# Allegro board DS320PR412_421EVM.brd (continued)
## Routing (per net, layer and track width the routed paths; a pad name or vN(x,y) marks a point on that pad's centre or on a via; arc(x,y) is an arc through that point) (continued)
N16831849: length 2.9
  BOTTOM w0.127: R9.2 JMP3.2
N16831858: length 2.9
  BOTTOM w0.127: R10.2 JMP3.4
N16831867: length 2.9
  BOTTOM w0.127: R11.1 JMP3.6
N16831870: length 2.9
  BOTTOM w0.127: R12.2 JMP3.8
N16832723: length 2.9
  BOTTOM w0.127: R21.2 JMP4.2
N16832755: length 2.9
  BOTTOM w0.127: R22.2 JMP4.4
N16832773: length 2.9
  BOTTOM w0.127: R23.1 JMP4.6
N16832779: length 2.9
  BOTTOM w0.127: R24.2 JMP4.8
N16832807: length 2.9
  BOTTOM w0.127: R25.2 JMP5.2
N16832839: length 2.9
  BOTTOM w0.127: R26.2 JMP5.4
N16832857: length 2.9
  BOTTOM w0.127: R27.1 JMP5.6
N16832863: length 2.9
  BOTTOM w0.127: R28.2 JMP5.8
N16832891: length 2.9
  BOTTOM w0.127: R29.2 JMP6.2
N16832923: length 2.9
  BOTTOM w0.127: R30.2 JMP6.4
N16832941: length 2.9
  BOTTOM w0.127: R39.1 JMP6.6
N16832947: length 2.9
  BOTTOM w0.127: R40.2 JMP6.8
N16833662: length 2.9
  BOTTOM w0.127: R49.2 JMP9.2
N16833694: length 2.9
  BOTTOM w0.127: R50.2 JMP9.4
N16833712: length 2.9
  BOTTOM w0.127: R51.1 JMP9.6
N16833718: length 2.9
  BOTTOM w0.127: R52.2 JMP9.8
N16833746: length 2.9
  BOTTOM w0.127: R53.2 JMP10.2
N16833778: length 2.9
  BOTTOM w0.127: R62.2 JMP10.4
N16833796: length 2.9
  BOTTOM w0.127: R63.1 JMP10.6
N16833802: length 2.9
  BOTTOM w0.127: R64.2 52.96,128.98
N16833830: length 2.9
  BOTTOM w0.127: R65.2 JMP11.2
N16833862: length 2.9
  BOTTOM w0.127: R66.2 JMP11.4
N16833880: length 2.9
  BOTTOM w0.127: R67.1 JMP11.6
N16833886: length 2.9
  BOTTOM w0.127: R68.2 JMP11.8
N16835436: length 2.9
  BOTTOM w0.127: R133.2 JMP14.2
N16835468: length 2.9
  BOTTOM w0.127: R134.2 74.04,128.98
N16835486: length 2.9
  BOTTOM w0.127: R135.1 JMP14.6
N16835492: length 2.9
  BOTTOM w0.127: R136.2 79.12,128.98
N16835520: length 2.9
  BOTTOM w0.127: R137.2 JMP15.2
N16835552: length 2.9
  BOTTOM w0.127: R138.2 JMP15.4
N16835570: length 2.9
  BOTTOM w0.127: R139.1 JMP15.6
N16835576: length 2.9
  BOTTOM w0.127: R140.2 JMP15.8
N16835604: length 2.9
  BOTTOM w0.127: R141.2 JMP16.2
N16835636: length 2.9
  BOTTOM w0.127: R142.2 JMP16.4
N16835654: length 2.9
  BOTTOM w0.127: R143.1 JMP16.6
N16835660: length 2.9
  BOTTOM w0.127: R144.2 JMP16.8
N16837171: length 2.6
  BOTTOM w0.127: R13.2 J30.2
N16837180: length 2.6
  BOTTOM w0.127: R14.2 J30.4
N16837189: length 2.6
  BOTTOM w0.127: R15.1 J30.6
N16837198: length 2.6
  BOTTOM w0.127: R16.2 J30.8
N16837577: length 2.6
  BOTTOM w0.127: R17.2 J23.2
N16837609: length 2.6
  BOTTOM w0.127: R18.2 J23.4
N16837629: length 2.6
  BOTTOM w0.127: R19.1 J23.6
N16837647: length 2.6
  BOTTOM w0.127: R20.2 J23.8
N16841214: length 2.6
  BOTTOM w0.127: R41.2 J24.2
N16841246: length 2.6
  BOTTOM w0.127: R42.2 J24.4
N16841266: length 2.6
  BOTTOM w0.127: R43.1 J24.6
N16841284: length 2.6
  BOTTOM w0.127: R44.2 J24.8
N16842142: length 2.6
  BOTTOM w0.127: R45.2 J25.2
N16842174: length 2.6
  BOTTOM w0.127: R46.2 J25.4
N16842194: length 2.6
  BOTTOM w0.127: R47.1 146.18,117.42
N16842212: length 2.6
  BOTTOM w0.127: R48.2 J25.8
N16843638: length 2.6
  BOTTOM w0.127: R69.2 J26.2
N16843670: length 2.6
  BOTTOM w0.127: R70.2 J26.4
N16843690: length 2.6
  BOTTOM w0.127: R71.1 J26.6
N16843708: length 2.6
  BOTTOM w0.127: R72.2 J26.8
N16844326: length 2.6
  BOTTOM w0.127: R73.2 J27.2
N16844358: length 2.6
  BOTTOM w0.127: R74.2 J27.4
N16844378: length 2.6
  BOTTOM w0.127: R75.1 J27.6
N16844396: length 2.6
  BOTTOM w0.127: R76.2 J27.8
N16846395: length 2.6
  BOTTOM w0.127: R145.2 J28.2
N16846427: length 2.6
  BOTTOM w0.127: R146.2 J28.4
N16846447: length 2.6
  BOTTOM w0.127: R147.1 J28.6
N16846465: length 2.6
  BOTTOM w0.127: R148.2 J28.8
N16847091: length 2.6
  BOTTOM w0.127: R149.2 J29.2
N16847123: length 2.6
  BOTTOM w0.127: R150.2 J29.4
N16847143: length 2.6
  BOTTOM w0.127: R151.1 J29.6
N16847161: length 2.6
  BOTTOM w0.127: R152.2 J29.8

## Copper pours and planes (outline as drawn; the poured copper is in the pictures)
+3.3V on TOP: 1.27,25.43 4.6,25.43 5,25.02 5,21.23 4.98,21.21 4.98,20.09 5.61,19.46 15.11,19.46 16.48,20.83 16.48,25.45 18.54,25.45 19,24.99 19,21.01 20.55,19.46 28.91,19.46 30.33,20.88 30.33,25.5 32.49,25.5 32.92,25.07 32.92,21.31 34.85,19.38 42.62,19.38 44.37,21.13 44.37,25.35 44.35,25.37 46.35,25.37 46.86,24.87 46.86,17.45 45.82,16.41 4.14,16.41 1.24,19.3 1.24,25.4
+3.3V on TOP: 12.9,74.22 12.9,71.11 13.62,70.39 20.8,70.39 21.56,71.15 21.56,73.97 20.8,74.73 13.41,74.73
+3.3V on TOP: 23.42,90.7 26.56,90.7 26.77,90.91 26.77,101.1 26.79,101.13 26.42,101.51 23.64,101.51 23.21,101.07 23.21,90.91
+3.3V on L3_SIG: 162.05,84 162.05,111.2 47.45,111.2 38.13,120.52 8.31,120.52 4.57,116.79 4.57,111.25 4.62,111.2 4.62,92.38 8.75,88.25 8.75,82.24 6.5,80 6.5,40.74 1.22,35.46 1.22,16.38 37.78,16.38 37.78,36.26 37.08,36.96 17.4,36.96 16.72,37.63 16.72,66.8 28.19,78.27 28.19,104.85 156.72,104.85 156.72,84
+3.3VA on TOP: 54.31,2.62 54.31,23.52 54.79,24 54.79,48.11 55.09,48.41 55.09,50.77 55.63,50.77 55.75,50.65 55.75,23.19 54.99,22.43 54.99,2.62
+3.3VA on TOP: 55.09,91.41 55.63,91.41 55.75,91.29 55.75,86.72 54.79,86.72 54.79,89 55.09,89.31
+3.3VA on BOTTOM: 55.01,46.06 55.01,53.05 57.45,55.49 57.45,81.08 54.18,84.35 54.18,88.02 55.23,89.06 55.5,89.06 55.66,88.9 55.66,85.45 55.64,85.42 55.64,84.43 58.02,82.05 58.02,54.87 55.92,52.77 55.92,46.5 55.48,46.06
+3V on TOP: 53.11,48.82 53.09,48.84 53.09,52.96 54.08,53.95 54.08,58.47 52.4,60.15 45.99,60.15 44.78,58.94 42.03,58.94 41.83,59.15 41.83,61.14 43.45,62.76 53.81,62.76 55.8,60.77 55.8,53.42 53.8,51.41 53.8,48.82
+3V on TOP: 53.09,89.48 53.09,93.6 54.08,94.59 54.08,99.11 53.6,99.58 42.03,99.58 41.83,99.79 41.83,101.78 42.09,102.03 55.18,102.03 55.8,101.41 55.8,94.06 53.8,92.05 53.8,89.46 53.11,89.46
+3V on TOP: 52.32,2.62 52.32,16.71 53.01,16.71 53.01,2.62
+3V on BOTTOM: 3.96,29.59 3.96,33.28 13.05,33.28 13.83,32.49 13.83,29.57 17.96,29.57 17.96,33.32 28.22,33.32 28.85,32.69 28.85,29.59 31.83,29.59 31.83,33.63 40.77,33.63 42.12,32.28 42.12,29.62 45.85,29.62 45.85,37.54 45.13,38.26 2.77,38.26 1.11,36.61 1.11,29.59
+3V on BOTTOM: 54.99,2.62 54.99,15.37 52.31,15.37 52.31,8.3 53.14,7.47 53.14,5.92 53.29,5.92 53.29,2.62
+3V on L4_SIG: 44.42,102.39 44.42,46.89 46.06,45.25 46.06,28.03 55.19,18.9 55.19,11.2 52.11,11.2 52.11,15.3 41.67,25.73 41.67,31.6 38.84,34.44 38.84,36.68 40.51,38.35 40.51,102.31 40.67,102.48 44.34,102.48
+12V on TOP: 13.06,87.3 16,87.3 16.01,87.29 16.01,85.06 15.96,85.01 12.4,85.01 11.99,84.61 11.99,82.98 11.91,82.9 8.46,82.9 7.35,81.79 3.71,81.79 3.71,84.91 3.73,84.89 6.71,84.89 7.49,85.67 9.55,85.67 9.55,86.66 12.42,86.66
+12V on TOP: 45.75,11 48.01,11 48.01,2.62 45.36,2.62 45.36,5.59 45.72,5.59 45.75,5.61
+12V on TOP: 47.07,57.99 48.74,57.99 48.79,57.94 48.79,46.35 48.72,46.28 46.18,46.28 46.08,46.38 46.08,52.65 47.09,53.67 47.09,57.96
+12V on TOP: 47.07,98.63 48.74,98.63 48.79,98.58 48.79,86.99 48.72,86.92 46.18,86.92 46.08,87.02 46.08,93.29 47.09,94.31 47.09,98.6
+12V on BOTTOM: 46.28,2.62 46.28,11 48.01,11 48.01,2.62
+12V on BOTTOM: 12.17,86.1 23.34,86.1 23.46,86.23 48.59,86.23 48.98,86.62 48.98,88.99 48.59,89.38 31.39,89.38 28.88,91.89 8.24,91.89 7.11,90.76 7.14,90.73 7.14,85.47 6.58,84.91 6.38,84.91 6.35,84.94 3.73,84.94 3.73,81.79 12.17,81.79
+12V on L3_SIG: 46.43,90.91 48.4,90.91 48.93,90.38 48.93,86.52 47.04,84.62 47.04,58.24 45.76,56.96 45.76,51.81 47.93,49.64 47.96,49.64 48.88,48.73 48.88,45.72 47.29,44.14 47.29,16.61 49.71,14.19 49.71,6.16 49.71,6.15 49.71,5.53 49.57,5.39 45.72,5.39 45.72,12.57 44.69,13.59 41.27,13.59 40.4,14.47 40.4,17.91 39.01,19.29 39.01,36.88 40.4,38.26 40.4,84.87
GND on TOP: 48.36,2.62 48.36,7.21 48.97,7.21 48.97,2.62
GND on TOP: 18.67,64.98 20.19,64.98 20.53,64.64 20.53,62.39 20.33,62.2 18.67,62.2 18.52,62.35 18.52,64.82
GND on TOP: 7.44,89.61 16.21,89.61 20.01,93.41 20.01,102.84 20.51,103.34 28.61,103.34 29.89,102.06 29.89,93.55 27.3,93.55 27.09,93.76 27.09,101.35 26.69,101.75 23.35,101.75 22.96,101.37 22.96,98.72 22.65,98.41 22.65,88.15 20.49,88.15 19.72,87.38 19.72,81.77 19.6,81.65 16.43,81.65 16.26,81.82 16.26,82.42 16.17,82.5 15.12,82.5 15.04,82.58 14.57,82.58 13.89,83.26 12.93,83.26 12.93,84.05 13.87,84.05 14.62,83.3 16.14,83.3 16.32,83.48 16.32,87.29 15.98,87.63 12.9,87.63 12.75,87.48 9.17,87.48 9.14,87.5 9.14,86.39 7.47,86.39 7.42,86.44 7.42,87.63
GND on BOTTOM: 112.34,23.01 112.34,21 112.63,20.71 122.45,20.71 123.34,19.82 125.44,19.82 125.98,20.36 126.83,20.36 127.05,20.14 127.67,20.14 128.37,20.85 128.37,23.08 127.93,23.53 112.86,23.53
GND on BOTTOM: 72.5,22.95 88.71,22.95 89.1,22.55 89.1,20.82 88.95,20.67 87.73,20.67 87.16,20.1 84.29,20.1 83.64,20.74 72.45,20.74 72.32,20.87 72.32,22.76
GND on BOTTOM: 92.39,20.55 92.39,22.92 92.77,23.29 108.05,23.29 108.56,22.78 108.56,20.41 108.38,20.23 106.85,20.23 106.82,20.26 106.64,20.26 106.16,19.78 103.14,19.78 102.93,19.98 102.93,20.39 102.6,20.72 93.38,20.72 93.09,20.43 92.52,20.43
GND on BOTTOM: 48.36,2.62 48.97,2.62 48.97,7.21 48.36,7.21
GND on BOTTOM: 54.24,22.23 57.65,22.23 58.51,23.09 69.31,23.09 70.01,22.39 70.01,20.83 69.67,20.49 64.14,20.49 63.94,20.29 63.94,19.87 63.83,19.75 60.45,19.75 60.41,19.8 60.41,20.39 60.19,20.62 59.12,20.62 58.89,20.39 58.89,20.03 58.66,19.8 54.51,19.8 53.89,20.42 53.89,21.88
GND on L2_GND: 89.53,5.64 128.65,5.64 128.65,13.41 186.92,13.41 186.92,135.97 0.64,135.97 0.64,5.16 14.35,5.16 14.35,13.41 34.04,13.41 34.04,5.16 40.64,5.16 40.64,11 41.39,12.75 43.18,13.41 44.9,12.67 45.72,11 45.72,5.64 55.75,5.64 55.75,7.44 57.15,8.84 58.55,7.44 58.55,5.64 89.51,5.64 89.53,-65.33 154.94,-65.33 154.94,-61.52 89.56,-61.52 ; 74 cut-outs
GND on L5_GND: 89.53,5.64 128.65,5.64 128.65,13.41 186.87,13.41 186.87,135.97 0.64,135.97 0.64,5.16 14.35,5.16 14.35,13.41 34.04,13.41 34.04,5.16 40.64,5.16 40.64,11 41.39,12.75 43.18,13.41 44.9,12.67 45.72,11 45.72,5.64 55.75,5.64 55.75,7.44 57.15,8.84 58.55,7.44 58.55,5.64 89.51,5.64 89.53,-65.33 154.94,-65.33 154.94,-61.52 89.56,-61.52
VCC0 on BOTTOM: 34.39,32.26 34.39,28.75 35.16,27.99 52.49,27.99 54.88,30.38 54.88,32.96 56.49,34.57 108.66,34.57 111.27,31.96 111.27,19.02 110.59,18.34 108.48,18.34 108.16,18.66 104.54,18.66 103.64,17.75 98.59,17.75 98.44,17.9 98.44,19.36 98.65,19.57 102.82,19.57 102.96,19.43 106.72,19.43 106.83,19.55 109.08,19.55 109.29,19.75 109.29,24.24 108.13,25.4 108.13,30.24 107.13,31.24 59.5,31.24 53.88,25.62 34.17,25.62 32.41,27.38 32.41,32.26
VCC1 on BOTTOM: 46.35,29.64 46.35,35.92 50.52,40.08 129.98,40.08 133.18,36.89 133.18,19.88 131.9,18.6 123.31,18.6 122.72,18.01 117.65,18.01 117.38,18.28 117.38,19.45 117.48,19.56 118.54,19.56 119.06,19.04 122.41,19.04 122.79,19.42 125.72,19.42 125.85,19.56 129.81,19.56 130.31,20.06 130.31,33 127.6,35.71 124.2,35.71 124.17,35.74 58.98,35.74 58.96,35.72 50.25,35.72 48.41,33.88 48.41,29.64
VCC2 on BOTTOM: 4.47,32.31 6.5,32.31 6.5,26.87 11.59,21.78 49.82,21.78 52.17,19.44 58.78,19.44 58.86,19.36 58.86,18.95 58.99,18.83 60.39,18.83 60.63,19.07 65.28,19.07 65.36,18.99 65.36,18.26 65.24,18.14 57.86,18.14 57.45,18.54 11.4,18.54 4.47,25.45
VCC3 on BOTTOM: 18.41,32.26 20.45,32.26 20.45,27.53 23.29,24.69 55.71,24.69 56.61,25.58 89.93,25.58 92.03,23.48 92.03,19.77 91.07,18.81 85.75,18.81 84.66,17.72 79.23,17.72 79.1,17.85 79.1,19.36 79.33,19.59 80.3,19.59 80.98,18.91 80.98,18.88 83.72,18.88 84.52,19.68 89.49,19.68 90.02,20.21 90.02,22.63 89.21,23.44 57.41,23.44 56.58,22.61 22.38,22.61 18.41,26.57
N16707563 on TOP: 20.06,87.31 20.06,85.01 20.11,84.96 26.65,84.96 27,85.31 27,87.64 26.81,87.84 22.78,87.84 22.27,87.32 20.07,87.32
N16716349 on TOP: 15.32,68.35 19.39,68.35 19.67,68.06 19.67,65.49 19.56,65.37 18.43,65.37 18.14,65.08 18.14,61.97 17.97,61.8 15.47,61.8 15.19,62.08 15.19,63.26 15.45,63.52 16.42,63.52 16.99,64.08 16.99,64.43 17,64.44 17,65.03 16.72,65.31 15.4,65.31 15.13,65.57 15.13,68.16
N16716349 on BOTTOM: 12.93,59.25 12.93,52.17 13.77,51.33 21.54,51.33 22.25,52.04 22.25,57.37 18.15,61.47 18.15,63.4 15.23,63.4 15.23,61.55
N16716349 on L4_SIG: 14.58,61.83 17.28,61.83 17.54,62.09 17.54,63.4 17.28,63.66 14.58,63.66 14.32,63.4 14.32,62.09
N16850880 on TOP: 35.44,32.8 34.96,32.31 34.96,28.49 36.01,27.44 36.01,20.97 35.97,20.93 36.52,20.37 40.4,20.37 40.9,20.87 40.9,31.34 39.44,32.8
N16850966 on TOP: 48.93,32.82 48.93,28.49 48.95,28.47 48.95,26.26 49.98,25.23 49.98,20.97 49.94,20.93 50.49,20.37 52.77,20.37 53.41,21.02 53.41,32.82
N16851615 on TOP: 7.5,32.8 7.02,32.31 7.02,28.49 8.07,27.44 8.07,20.97 8.03,20.93 8.58,20.37 12.46,20.37 12.96,20.87 12.96,31.34 11.5,32.8
N16851807 on TOP: 21.47,32.8 20.99,32.31 20.99,28.49 22.04,27.44 22.04,20.97 22,20.93 22.55,20.37 26.43,20.37 26.93,20.87 26.93,31.34 25.47,32.8

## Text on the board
BOTTOM: LAYER 6 - BOTTOM SIDE
Ref Des/Assembly Bottom: ASSY BOTTOM
Board Geometry/Soldermask Bottom: SOLDERMASK BOTTOM
Package Geometry/Pastemask Bottom: PASTEMASK BOTTOM
Ref Des/Silkscreen Bottom: SILKSCREEN BOTTOM
User.Comments: 1 | 2
TOP: LAYER 1 - TOP SIDE
Ref Des/Assembly Top: ASSY TOP
Board Geometry/Soldermask Top: SOLDERMASK TOP
Package Geometry/Pastemask Top: PASTEMASK TOP
Ref Des/Silkscreen Top: DS160PR421_2 | DS160PR421_3 | DS160PR412_0 | DS160PR412_1 | 3_1 | 2_1 | PRSNT3_1 | PRSNT2_1 | GND | 2_1_B | 2_1_A | 2_3_B | 2_3_A | 2_2 | 2_4 | PRSNT2_2 | PRSNT2_4 | 2_2_B | 2_2_A | 2_4_B | 2_4_A | A | 12V | REFOUT | CLKIN1 | CLKIN0 | DISABLE | ENABLED | DISABLED | SELECT | USB2ANY | AARDVARK | CONN | A+B | B | NC=L4 | CLKIN1- | 3.3V | CLKIN1+ | PCIE | VCC2 | REG | VCC3 | PERRST#A | PERRST#A+B | PERRST#B | L0 | VCC0 | L1 | L2 | L3 | VCC1 | SDA | SCL | PD | PERST_INV | PR421_2_VCC | PR421_3_VCC | PR412_0_VCC | PR412_1_VCC | 421_2 GAIN | 421_2 MODE | 421_2 RX_DET | 421_3 EQ0_ADDR | 421_3 GAIN | 421_3 RX_DET | 412_0 EQ0_ADDR | 412_0 GAIN | 412_0 EQ1 | 412_0 RX_DET | 412_1 GAIN | 412_1 RX_DET | PCIe-A X8 | PCIe-B X16 | SILKSCREEN TOP | LABEL | HSDC110A
L2_GND: LAYER 2 - GND PLANE
L3_SIG: LAYER 3 - SIGNAL
L4_SIG: LAYER 4 - SIGNAL
L5_GND: LAYER 5 - GND PLANE
XSECTION_CHART: * AIR 0 MIL | * SOLDERMASK-0.8MIL 0.8 MIL | L1 COPPER_1/2OZ_PLATED 1.4 MIL | * FILL_RO4450T_3 3 MIL | L2 COPPER_1.0OZ 1.4 MIL | L3 COPPER_1.0OZ 1.4 MIL | * CORE_RO4350B_20 20 MIL | L4 COPPER_1.0OZ 1.4 MIL | L5 COPPER_1.0OZ 1.4 MIL | L6 COPPER_1/2OZ_PLATED 1.4 MIL | DESIGN CROSS SECTION CHART | ___________________________ | TOTAL THICKNESS 62 MIL | 1-6
DIMENSION: FABRICATION DRAWING | CAD ORIGIN | 0.050 | TYP | SCALE: NONE | BEVEL EDGE DETAIL | VIEW A-A
User.6: LAYER 5 | LAYER 1 | LAYER 2 | LAYER 3 | LAYER 4 | LAYER 6 | LAYER | NO. | TABLE 1: | L5_GND | TOP | L2_GND | L3_SIG | L4_SIG | BOTTOM | NAME | DIFFIRENTIAL PAIR | IMPEDANCE (OHMS) | 85 +/- 10% | DIFF TRACE | WIDTH | 0.004" | 0.005" | SPACING | 0.006" | 0.0055" | SINGLE ENDED | 50 +/- 10% | TRACE WIDTH | REFERENCE | SEE VIEW A-A | SEE SPECIAL FAB NOTE 1 | SPECIAL FAB NOTES: | 1. SELECTIVE HARD GOLD PLATNG TO BE FLAT PLATED 30uIN(MINIMUM) OF Au OVER 150-200uIN OF nI GOLD | PLATING. PLATING ON PAD SHOULD BE THE SAME LEVEL OR ABOVE THE SOLDER RESIST SURFACE ON TOP | PLACE DRILL CHART HERE: | AND BOTTOM. | MIN. ANNULAR RING 2 MIL EXTERNAL PER IPC-6012C | REGISTRATION TOLERANCES: METAL +/- X MIL,HOLES +/- X MIL | IMPEDANCE CONTROL: | BOARD SIZE (REFER ALSO ARRAY/PANEL PROFILING INFORMATION) | MIXED DIELECTRIC: | LAMINATE MATERIAL: | THICKNESS: | TOLERANCE: | COPPER THICKNESS (FINISHED): | BOARD FINISH: | NUMBER OF LAYERS: | MIN. TRACK WIDTH: | MIN. CLEARANCE  : | MIN. VIA PAD/DRILL: | THIEVING ALLOWED: | X | OUTER: | INNER SIGNAL: | INNER PLANE: | OTHER: | SILKSCREEN: | SOLDERMASK: (PER IPC-6011,6012) | BOARD SURFACE TREATMENT: | ADDITIONAL REQUIREMENTS: | VENDOR MARKING: | SILKSCREEN COLOR: | SOLDERMASK COLOR: | THROUGH-HOLE VIA TREATMENT: | VIA FILL USING COPPER AND PLATED OVER SMOOTH | VIA FILL USING NON-CONDUCTIVE EPOXY AND PLATED OVER SMOOTH | FOR WIRE BONDING: | VENDOR DATE CODE,UL,LOGO: | FR-4 HIGH Tg | 0.062" +/-10% | IPC-6012C CLASS 2 | IPC-6012C CLASS 3 | MICRO-SECTION | CERTIFICATES OF COMPLIANCE | NICKEL/GOLD (ENIG) | IMMERSION TIN | HARD GOLD | IN AN OPEN AREA | 1/4 OZ. | OPEN | NO | 6 | 4.0 MIL | 7.8 MIL | 20/10 MIL | NONE | DESIGN INFORMATION | ROGERS 4350B | 0.093" +/-10% | YES | TDR REPORTS/COUPONS | WHITE | GREEN | SOFT GOLD | TENTED | 1/2 OZ. | BOW & TWIST: | ORGANIC (OSP) | OTHER | WHERE INDICATED (SEE DRAWING) | YES - SEE TABLE 1 | ETCH | IDENTIFIER: | BLUE | RoHS | 1.0 OZ. | SILKSCREEN | PER SUPPLIED ARTWORK | ALL x MIL VIAS | ALL LASER DRILLS | ALL MECH VIAS | ELECTRICAL TEST | UL 94V-0 | HASL | 2.0 OZ. | BREAK-AWAY | ENEPIG
User.10: FIGURE | FINISHED_SIZE | 10.0 | 15.75 | 40.16 | 125.0 | 47.24 | DRILL CHART: TOP to BOTTOM | ALL UNITS ARE IN MILS | TOLERANCE_DRILL | +3.0/-3.0 | +3.15/-3.15 | +1.97/-1.97 | PLATED | NON-PLATED | QTY | 1023 | 24 | 282 | 2 | 4 | 1335 | TOTAL HOLES:
